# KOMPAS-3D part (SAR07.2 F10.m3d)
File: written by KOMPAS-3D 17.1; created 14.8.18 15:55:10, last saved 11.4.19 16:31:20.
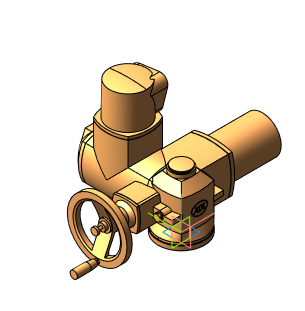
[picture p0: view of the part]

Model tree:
1. Операция без истории:3  (labels: Сталь 20  ГОСТ 1050-2013)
